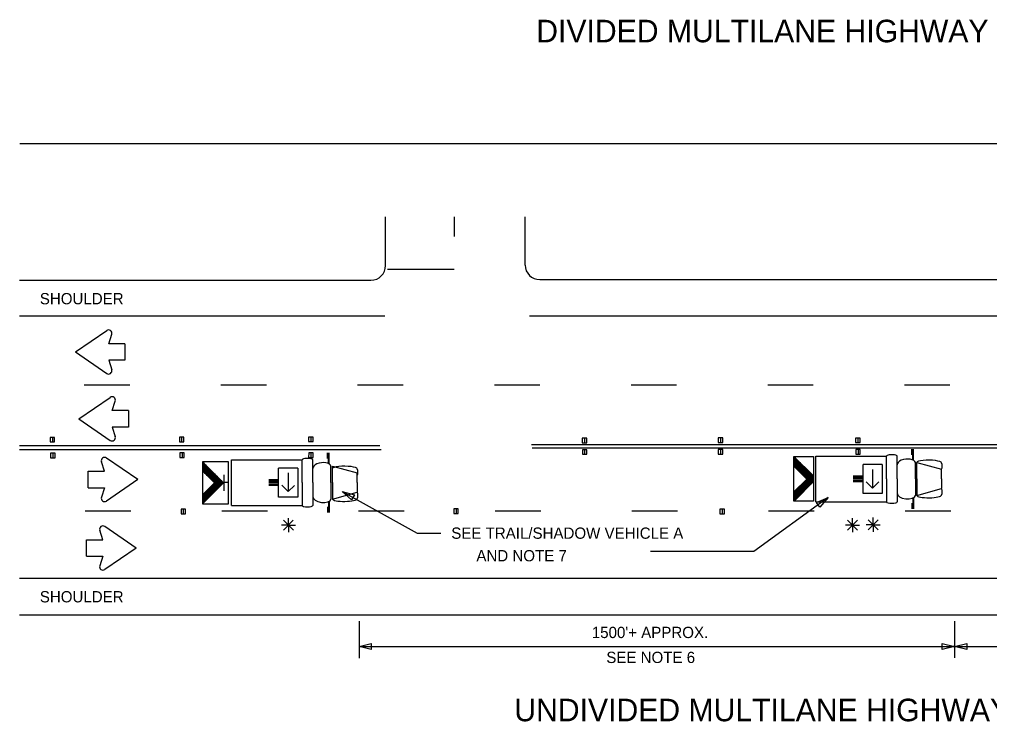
# Model space of a CAD drawing. Extents: x -747 to 834, y -5485 to -3577.
# Drawn here: x -747 to -231, y -5448 to -5075 of the extents above; entities that cross this region are included whole.
import ezdxf

# ---------------------------------------------------------------- set-up
doc = ezdxf.new("R2010")
doc.units = 0
doc.layers.add('Level 1', color=7, linetype='Continuous')
doc.layers.add('Working Level 1', color=7, linetype='Continuous')

msp = doc.modelspace()

# ---------------------------------------------------------------- linework, layer by layer
at = {"layer": 'Level 1'}
for points in [[(-575.22, -5325.83), (-535.37, -5348.13), (-522.83, -5348.13)], [(-316.65, -5329.18), (-356.21, -5357.89), (-411.1, -5357.89)]]:
    msp.add_lwpolyline(points, dxfattribs=at)
at = {"layer": 'Working Level 1'}
for p, q in [((-746.8, -5140.74), (52.65, -5140.74)), ((-552.16, -5205.71), (-552.16, -5179.72)), ((-477.84, -5205.41), (-477.84, -5179.72)), ((-551.1, -5207.58), (-515.63, -5207.58)), ((-747.06, -5213.47), (-559.92, -5213.47)), ((-470.08, -5213.17), (52.99, -5213.17)), ((-747.06, -5232.41), (-552.5, -5232.41)), ((-475.5, -5232.41), (52.99, -5232.41)), ((-717.25, -5251.67), (-700.58, -5240.23)), ((-699.53, -5247.3), (-697.9, -5242.23)), ((-717.25, -5251.67), (-700.58, -5263.1)), ((-690.86, -5247.3), (-699.53, -5247.3)), ((-690.86, -5247.3), (-690.86, -5256.03)), ((-690.86, -5256.03), (-699.53, -5256.03)), ((-699.53, -5256.03), (-697.9, -5261.1)), ((-715.39, -5287.25), (-698.72, -5275.81)), ((-697.67, -5282.88), (-696.04, -5277.81)), ((-688.99, -5282.88), (-697.67, -5282.88)), ((-688.99, -5282.88), (-688.99, -5291.61)), ((-715.39, -5287.25), (-698.72, -5298.68)), ((-688.99, -5291.61), (-697.67, -5291.61)), ((-697.67, -5291.61), (-696.04, -5296.69)), ((-730.72, -5297.13), (-730.73, -5299.56)), ((-728.3, -5297.13), (-730.72, -5297.13)), ((-729.51, -5297.13), (-729.51, -5299.56)), ((-728.3, -5299.56), (-728.3, -5297.13)), ((-659.49, -5297.02), (-661.92, -5297.02)), ((-661.92, -5297.02), (-661.92, -5299.45)), ((-660.7, -5297.02), (-660.7, -5299.45)), ((-659.49, -5299.45), (-659.49, -5297.02)), ((-593.17, -5296.91), (-593.18, -5299.34)), ((-590.75, -5296.91), (-593.17, -5296.91)), ((-591.96, -5296.91), (-591.96, -5299.34)), ((-590.75, -5299.34), (-590.75, -5296.91)), ((-445.1, -5297.55), (-447.53, -5297.55)), ((-447.53, -5297.55), (-447.53, -5299.98)), ((-446.31, -5297.55), (-446.31, -5299.98)), ((-445.1, -5299.98), (-445.1, -5297.55)), ((-372.66, -5297.37), (-375.09, -5297.37)), ((-375.09, -5297.37), (-375.09, -5299.8)), ((-373.87, -5297.37), (-373.87, -5299.8)), ((-372.66, -5299.8), (-372.66, -5297.37)), ((-301.99, -5297.45), (-302, -5299.88)), ((-299.57, -5297.45), (-301.99, -5297.45)), ((-300.78, -5297.45), (-300.78, -5299.88)), ((-299.57, -5299.88), (-299.57, -5297.45)), ((-747.06, -5301.43), (-555.26, -5301.43)), ((-747.06, -5303.54), (-554.46, -5303.54)), ((-730.73, -5299.56), (-728.3, -5299.56)), ((-661.92, -5299.45), (-659.49, -5299.45)), ((-593.18, -5299.34), (-590.75, -5299.34)), ((-474.52, -5300.89), (52.99, -5300.89)), ((-474.18, -5302.58), (52.99, -5302.58)), ((-447.53, -5299.98), (-445.1, -5299.98)), ((-375.09, -5299.8), (-372.66, -5299.8)), ((-372.63, -5303.55), (-375.06, -5303.55)), ((-375.06, -5303.55), (-375.06, -5305.98)), ((-373.84, -5303.55), (-373.85, -5305.98)), ((-372.63, -5305.98), (-372.63, -5303.55)), ((-302, -5299.88), (-299.57, -5299.88)), ((-272.05, -5306.39), (-272.05, -5303.42)), ((-271.58, -5309.25), (-271.58, -5303.42)), ((-271.18, -5309.25), (-271.18, -5303.42)), ((-728.09, -5305.5), (-730.52, -5305.5)), ((-730.52, -5305.5), (-730.52, -5307.93)), ((-730.52, -5307.93), (-728.09, -5307.93)), ((-729.3, -5305.5), (-729.31, -5307.93)), ((-728.09, -5307.93), (-728.09, -5305.5)), ((-684.06, -5319.53), (-700.73, -5308.09)), ((-661.71, -5305.39), (-661.72, -5307.82)), ((-661.72, -5307.82), (-659.29, -5307.82)), ((-659.29, -5305.39), (-661.71, -5305.39)), ((-660.5, -5305.39), (-660.5, -5307.82)), ((-659.29, -5307.82), (-659.29, -5305.39)), ((-593.09, -5305.39), (-593.1, -5307.82)), ((-593.1, -5307.82), (-590.67, -5307.82)), ((-590.67, -5305.39), (-593.09, -5305.39)), ((-591.88, -5305.39), (-591.88, -5307.82)), ((-590.67, -5307.82), (-590.67, -5305.39)), ((-583.09, -5308.32), (-583.09, -5305.35)), ((-582.62, -5311.18), (-582.62, -5305.35)), ((-582.23, -5311.18), (-582.23, -5305.35)), ((-444.99, -5303.66), (-447.42, -5303.66)), ((-447.42, -5303.66), (-447.42, -5306.09)), ((-447.42, -5306.09), (-444.99, -5306.09)), ((-446.2, -5303.66), (-446.2, -5306.09)), ((-444.99, -5306.09), (-444.99, -5303.66)), ((-375.06, -5305.98), (-372.63, -5305.98)), ((-334.81, -5307.3), (-324.45, -5317.65)), ((-323.1, -5307.12), (-285.56, -5307.12)), ((-323.1, -5331.37), (-323.1, -5307.12)), ((-299.46, -5303.62), (-301.89, -5303.62)), ((-301.89, -5303.62), (-301.89, -5306.05)), ((-301.89, -5306.05), (-299.46, -5306.05)), ((-300.67, -5303.62), (-300.67, -5306.05)), ((-299.46, -5306.05), (-299.46, -5303.62)), ((-285.56, -5319.24), (-285.56, -5307.12)), ((-279.8, -5319.24), (-279.8, -5307.12)), ((-701.78, -5315.16), (-703.41, -5310.09)), ((-649.63, -5310.09), (-638.44, -5321.26)), ((-634.15, -5309.05), (-596.6, -5309.05)), ((-634.15, -5333.3), (-634.15, -5309.05)), ((-598.8, -5313.41), (-609.07, -5313.41)), ((-609.07, -5328.94), (-609.07, -5313.41)), ((-598.8, -5313.41), (-598.8, -5328.94)), ((-596.6, -5321.17), (-596.6, -5309.05)), ((-590.85, -5321.17), (-590.85, -5309.05)), ((-581.21, -5321.17), (-581.21, -5312.44)), ((-580.41, -5312.44), (-567.28, -5316.03)), ((-580.41, -5321.17), (-580.41, -5312.44)), ((-334.81, -5312.47), (-327.97, -5319.28)), ((-287.76, -5311.48), (-298.02, -5311.48)), ((-298.02, -5327.01), (-298.02, -5311.48)), ((-287.76, -5311.48), (-287.76, -5327.01)), ((-270.17, -5319.24), (-270.17, -5310.51)), ((-269.37, -5310.51), (-256.24, -5314.1)), ((-269.37, -5319.24), (-269.37, -5310.51)), ((-710.46, -5323.89), (-710.46, -5315.16)), ((-710.46, -5315.16), (-701.78, -5315.16)), ((-649.63, -5314.94), (-643.21, -5321.32)), ((-638.07, -5325.46), (-638.07, -5317.05)), ((-603.93, -5316.05), (-603.93, -5325.98)), ((-567.28, -5321.17), (-567.28, -5316.03)), ((-298.02, -5317.7), (-303.25, -5317.7)), ((-298.02, -5318.47), (-303.25, -5318.47)), ((-292.89, -5314.12), (-292.89, -5324.05)), ((-256.24, -5319.24), (-256.24, -5314.1)), ((-710.46, -5323.89), (-701.78, -5323.89)), ((-701.78, -5323.89), (-703.41, -5328.97)), ((-684.06, -5319.53), (-700.73, -5330.97)), ((-649.63, -5327.72), (-643.21, -5321.32)), ((-649.56, -5332.38), (-638.44, -5321.26)), ((-635.73, -5321.06), (-638.14, -5321.06)), ((-609.07, -5319.63), (-614.29, -5319.63)), ((-609.07, -5320.4), (-614.29, -5320.4)), ((-609.07, -5321.18), (-614.29, -5321.18)), ((-609.07, -5321.95), (-614.29, -5321.95)), ((-609.07, -5322.73), (-614.29, -5322.73)), ((-603.93, -5325.98), (-607.31, -5322.6)), ((-603.93, -5325.98), (-600.64, -5322.68)), ((-596.6, -5321.17), (-596.6, -5333.3)), ((-590.85, -5321.17), (-590.85, -5333.3)), ((-581.21, -5321.17), (-581.21, -5329.91)), ((-580.41, -5321.17), (-580.41, -5329.91)), ((-567.28, -5321.17), (-567.28, -5326.32)), ((-334.81, -5326.1), (-327.97, -5319.28)), ((-334.74, -5331.08), (-324.5, -5320.83)), ((-298.02, -5319.25), (-303.25, -5319.25)), ((-298.02, -5320.02), (-303.25, -5320.02)), ((-298.02, -5320.8), (-303.25, -5320.8)), ((-292.89, -5324.05), (-296.27, -5320.67)), ((-292.89, -5324.05), (-289.6, -5320.75)), ((-285.56, -5319.24), (-285.56, -5331.37)), ((-279.8, -5319.24), (-279.8, -5331.37)), ((-270.17, -5319.24), (-270.17, -5327.98)), ((-269.37, -5319.24), (-269.37, -5327.98)), ((-256.24, -5319.24), (-256.24, -5324.39)), ((-598.8, -5328.94), (-609.07, -5328.94)), ((-580.41, -5329.91), (-567.28, -5326.32)), ((-287.76, -5327.01), (-298.02, -5327.01)), ((-271.58, -5329.24), (-271.58, -5335.06)), ((-271.18, -5329.24), (-271.18, -5335.06)), ((-269.37, -5327.98), (-256.24, -5324.39)), ((-634.15, -5333.3), (-596.6, -5333.3)), ((-583.09, -5334.03), (-583.09, -5337)), ((-582.62, -5331.17), (-582.62, -5337)), ((-582.23, -5331.17), (-582.23, -5337)), ((-323.1, -5331.37), (-285.56, -5331.37)), ((-272.05, -5332.1), (-272.05, -5335.06)), ((-658.61, -5335.29), (-661.04, -5335.29)), ((-661.04, -5335.29), (-661.04, -5337.72)), ((-661.04, -5337.72), (-658.61, -5337.72)), ((-659.82, -5335.29), (-659.83, -5337.72)), ((-658.61, -5337.72), (-658.61, -5335.29)), ((-515.88, -5335.18), (-515.89, -5337.61)), ((-515.89, -5337.61), (-513.46, -5337.61)), ((-513.46, -5335.18), (-515.88, -5335.18)), ((-514.67, -5335.18), (-514.67, -5337.61)), ((-513.46, -5337.61), (-513.46, -5335.18)), ((-371.81, -5335.29), (-374.24, -5335.29)), ((-374.24, -5335.29), (-374.24, -5337.72)), ((-374.24, -5337.72), (-371.81, -5337.72)), ((-373.02, -5335.29), (-373.03, -5337.72)), ((-371.81, -5337.72), (-371.81, -5335.29)), ((-684.99, -5355.98), (-701.66, -5344.54)), ((-603.87, -5343.79), (-607.64, -5343.79)), ((-603.87, -5343.79), (-606.53, -5341.13)), ((-603.87, -5343.79), (-606.53, -5346.45)), ((-603.94, -5343.84), (-601.27, -5341.18)), ((-603.87, -5343.79), (-603.87, -5340.02)), ((-603.87, -5343.79), (-601.21, -5346.45)), ((-603.87, -5343.79), (-603.87, -5347.55)), ((-603.87, -5343.79), (-600.11, -5343.79)), ((-303.62, -5343.79), (-307.38, -5343.79)), ((-303.62, -5343.79), (-306.28, -5341.13)), ((-303.62, -5343.79), (-306.28, -5346.45)), ((-303.68, -5343.84), (-301.02, -5341.18)), ((-303.62, -5343.79), (-303.62, -5340.02)), ((-303.62, -5343.79), (-300.96, -5346.45)), ((-303.62, -5343.79), (-303.62, -5347.55)), ((-303.62, -5343.79), (-299.86, -5343.79)), ((-292.64, -5343.55), (-296.4, -5343.55)), ((-292.64, -5343.55), (-295.3, -5340.89)), ((-292.64, -5343.55), (-295.3, -5346.21)), ((-292.7, -5343.6), (-290.04, -5340.94)), ((-292.64, -5343.55), (-292.64, -5339.78)), ((-292.64, -5343.55), (-289.98, -5346.21)), ((-292.64, -5343.55), (-292.64, -5347.31)), ((-292.64, -5343.55), (-288.88, -5343.55)), ((-702.71, -5351.62), (-704.34, -5346.54)), ((-711.39, -5360.35), (-711.39, -5351.62)), ((-711.39, -5351.62), (-702.71, -5351.62)), ((-711.39, -5360.35), (-702.71, -5360.35)), ((-702.71, -5360.35), (-704.34, -5365.42)), ((-684.99, -5355.98), (-701.66, -5367.42)), ((-747.06, -5372.07), (52.99, -5372.07)), ((-747.06, -5391.46), (52.99, -5391.46)), ((-566.29, -5394.93), (-566.29, -5414.6)), ((-249.33, -5394.93), (-249.33, -5414.4)), ((-566.29, -5408.34), (-249.33, -5408.34)), ((-566.29, -5408.34), (-560.86, -5408.34)), ((-249.33, -5408.34), (-252.05, -5408.34)), ((-249.33, -5408.34), (-243.82, -5408.34)), ((-249.33, -5408.34), (-149.89, -5408.34))]:
    msp.add_line(p, q, dxfattribs=at)
for points in [[(-515.67, -5179.72), (-515.67, -5190.19)], [(-712.53, -5269.15), (-688.27, -5269.15)], [(-639.77, -5269.15), (-615.52, -5269.15)], [(-567.02, -5269.15), (-542.76, -5269.15)], [(-494.26, -5269.15), (-470.01, -5269.15)], [(-421.51, -5269.15), (-397.25, -5269.15)], [(-348.75, -5269.15), (-324.5, -5269.15)], [(-276, -5269.15), (-251.74, -5269.15)], [(-334.81, -5307.85), (-328.52, -5318.75)], [(-334.28, -5307.82), (-325.95, -5322.26)], [(-649.63, -5310.61), (-643.72, -5320.83)], [(-649.63, -5311.48), (-644.89, -5319.69)], [(-649.63, -5312.37), (-646.06, -5318.54)], [(-649.63, -5313.24), (-647.23, -5317.39)], [(-649.13, -5310.58), (-641.32, -5324.12)], [(-647.93, -5311.78), (-640.99, -5323.8)], [(-646.74, -5312.97), (-640.67, -5323.47)], [(-334.81, -5308.79), (-329.76, -5317.54)], [(-334.81, -5309.73), (-331.01, -5316.31)], [(-334.81, -5310.66), (-332.25, -5315.09)], [(-334.81, -5311.61), (-333.5, -5313.87)], [(-334.81, -5312.54), (-334.74, -5312.65)], [(-333, -5309.1), (-325.6, -5321.92)], [(-331.72, -5310.38), (-325.26, -5321.58)], [(-330.44, -5311.66), (-324.91, -5321.24)], [(-329.17, -5312.93), (-324.57, -5320.89)], [(-649.63, -5314.13), (-648.39, -5316.25)], [(-649.63, -5315.01), (-649.56, -5315.1)], [(-645.53, -5314.18), (-640.35, -5323.16)], [(-644.34, -5315.37), (-640.03, -5322.83)], [(-643.14, -5316.58), (-639.69, -5322.53)], [(-641.94, -5317.77), (-639.36, -5322.23)], [(-640.74, -5318.96), (-639.07, -5321.86)], [(-327.89, -5314.21), (-324.49, -5320.1)], [(-326.61, -5315.49), (-324.47, -5319.18)], [(-325.33, -5316.76), (-324.46, -5318.28)], [(-645.94, -5324.03), (-644.22, -5327)], [(-645.61, -5323.71), (-643.89, -5326.69)], [(-645.29, -5323.39), (-643.57, -5326.36)], [(-644.97, -5323.07), (-643.25, -5326.04)], [(-644.65, -5322.74), (-642.92, -5325.72)], [(-644.33, -5322.42), (-642.6, -5325.4)], [(-644, -5322.11), (-642.28, -5325.08)], [(-643.69, -5321.78), (-641.95, -5324.76)], [(-643.36, -5321.46), (-641.63, -5324.44)], [(-639.63, -5320.05), (-638.77, -5321.55)], [(-332.59, -5323.89), (-330.76, -5327.05)], [(-332.24, -5323.54), (-330.41, -5326.71)], [(-331.9, -5323.2), (-330.07, -5326.37)], [(-331.56, -5322.85), (-329.73, -5326.02)], [(-331.21, -5322.51), (-329.38, -5325.68)], [(-330.87, -5322.17), (-329.04, -5325.34)], [(-330.53, -5321.82), (-328.69, -5325)], [(-330.19, -5321.48), (-328.35, -5324.66)], [(-329.84, -5321.14), (-328.01, -5324.32)], [(-329.5, -5320.8), (-327.66, -5323.97)], [(-329.16, -5320.45), (-327.32, -5323.63)], [(-328.81, -5320.11), (-326.98, -5323.29)], [(-328.47, -5319.77), (-326.63, -5322.94)], [(-328.12, -5319.42), (-326.29, -5322.61)], [(-649.63, -5328.19), (-648.08, -5330.85)], [(-649.63, -5329.07), (-648.41, -5331.18)], [(-649.48, -5327.57), (-647.76, -5330.53)], [(-649.15, -5327.24), (-647.44, -5330.21)], [(-648.83, -5326.93), (-647.12, -5329.89)], [(-648.51, -5326.6), (-646.79, -5329.57)], [(-648.19, -5326.28), (-646.47, -5329.24)], [(-647.87, -5325.96), (-646.15, -5328.93)], [(-647.55, -5325.64), (-645.83, -5328.61)], [(-647.22, -5325.32), (-645.5, -5328.29)], [(-646.9, -5325), (-645.18, -5327.97)], [(-646.58, -5324.67), (-644.86, -5327.64)], [(-646.26, -5324.35), (-644.54, -5327.32)], [(-334.81, -5326.6), (-333.16, -5329.45)], [(-334.81, -5327.54), (-333.51, -5329.79)], [(-334.81, -5328.48), (-333.85, -5330.13)], [(-334.65, -5325.94), (-332.82, -5329.1)], [(-334.3, -5325.59), (-332.48, -5328.76)], [(-333.96, -5325.26), (-332.14, -5328.42)], [(-333.61, -5324.91), (-331.79, -5328.08)], [(-333.28, -5324.57), (-331.45, -5327.73)], [(-332.93, -5324.23), (-331.1, -5327.4)], [(-649.63, -5329.95), (-648.73, -5331.5)], [(-649.63, -5330.83), (-649.05, -5331.82)], [(-649.63, -5331.71), (-649.38, -5332.13)], [(-334.81, -5329.42), (-334.2, -5330.48)], [(-334.81, -5330.36), (-334.54, -5330.81)], [(-712.09, -5336.14), (-687.83, -5336.14)], [(-639.33, -5336.14), (-615.08, -5336.14)], [(-566.58, -5336.14), (-542.32, -5336.14)], [(-493.82, -5336.14), (-469.57, -5336.14)], [(-421.07, -5336.14), (-396.82, -5336.14)], [(-348.32, -5336.14), (-324.06, -5336.14)], [(-275.56, -5336.14), (-251.31, -5336.14)]]:
    msp.add_lwpolyline(points, dxfattribs=at)
for points in [[(-324.42, -5331.08), (-334.81, -5331.08), (-334.81, -5307.3), (-324.42, -5307.3)], [(-649.63, -5310.09), (-649.63, -5332.39), (-635.69, -5332.39), (-635.69, -5310.09)], [(-570.34, -5330.42), (-575.22, -5325.83), (-568.75, -5327.59)], [(-322.86, -5331.68), (-316.65, -5329.18), (-320.96, -5334.31)], [(-559.79, -5409.96), (-566.29, -5408.34), (-559.79, -5406.71)], [(-255.83, -5406.71), (-249.33, -5408.34), (-255.83, -5409.96)], [(-242.83, -5409.96), (-249.33, -5408.34), (-242.83, -5406.71)]]:
    msp.add_lwpolyline(points, close=True, dxfattribs=at)
for centre, radius, start, end in [((-470.09, -5205.41), 7.76, 180, 270), ((-559.92, -5205.71), 7.76, 270, 360), ((-699.59, -5241.69), 1.77, 342.1824, 124.4455), ((-699.59, -5261.64), 1.77, 235.5545, 17.8176), ((-697.72, -5277.27), 1.77, 342.1824, 124.4455), ((-697.72, -5297.22), 1.77, 235.5545, 17.8176), ((-701.73, -5309.56), 1.77, 55.5545, 197.8176), ((-570.5, -5315.59), 3.64, 331.8801, 28.1199), ((-259.45, -5312.38), 3.64, 331.8801, 28.1199), ((-701.73, -5329.51), 1.77, 162.1824, 304.4455), ((-570.5, -5328.04), 3.64, 331.8801, 28.1199), ((-259.45, -5326.11), 3.64, 331.8801, 28.1199), ((-702.65, -5346), 1.77, 55.5545, 197.8176), ((-702.65, -5365.96), 1.77, 162.1824, 304.4455)]:
    msp.add_arc(centre, radius, start, end, dxfattribs=at)
for centre, major_axis, ratio, start_param, end_param in [((-593.73, -5309.05), (2.88, 0), 0.269913, 0, 3.141593), ((-282.68, -5307.12), (2.88, 0), 0.269913, 0, 3.141593), ((-274.99, -5311.11), (4.82, 0.6), 0.503092, 0, 3.141593), ((-586.03, -5313.04), (4.82, 0.6), 0.503092, 0, 3.141593), ((-573.85, -5313.79), (6.56, -0.08), 0.2034, 0, 3.141593), ((-262.8, -5310.58), (6.56, -0.08), 0.2034, 0, 3.141593), ((-586.03, -5329.31), (4.82, -0.6), 0.503092, 3.141593, 6.283185), ((-274.99, -5327.38), (4.82, -0.6), 0.503092, 3.141593, 6.283185), ((-262.8, -5327.9), (6.56, 0.08), 0.2034, 3.141593, 6.283185), ((-593.73, -5333.3), (2.88, 0), 0.269913, 3.141593, 6.283185), ((-573.85, -5329.83), (6.56, 0.08), 0.2034, 3.141593, 6.283185), ((-282.68, -5331.37), (2.88, 0), 0.269913, 3.141593, 6.283185)]:
    msp.add_ellipse(centre, major_axis=major_axis, ratio=ratio, start_param=start_param, end_param=end_param, dxfattribs=at)

# ---------------------------------------------------------------- texts
for s, height, p in [('DIVIDED MULTILANE HIGHWAY', 12, (-471.95, -5086.9)), ('SHOULDER', 6, (-736.19, -5226.3)), ('SHOULDER', 6, (-736.19, -5384.9)), ('UNDIVIDED MULTILANE HIGHWAY', 12, (-483.65, -5448.15))]:
    msp.add_text(s, height=height, rotation=0, dxfattribs=at).set_placement(p)
for s, p in [('SEE TRAIL/SHADOW VEHICLE A', (-517.19, -5351.06)), ('      AND NOTE 7', (-517.19, -5363.06)), ("1500'+ APPROX.", (-442.39, -5403.88)), ('SEE NOTE 6', (-434.67, -5417.16))]:
    msp.add_text(s, height=6, dxfattribs=at).set_placement(p)

doc.saveas('drawing.dxf')
